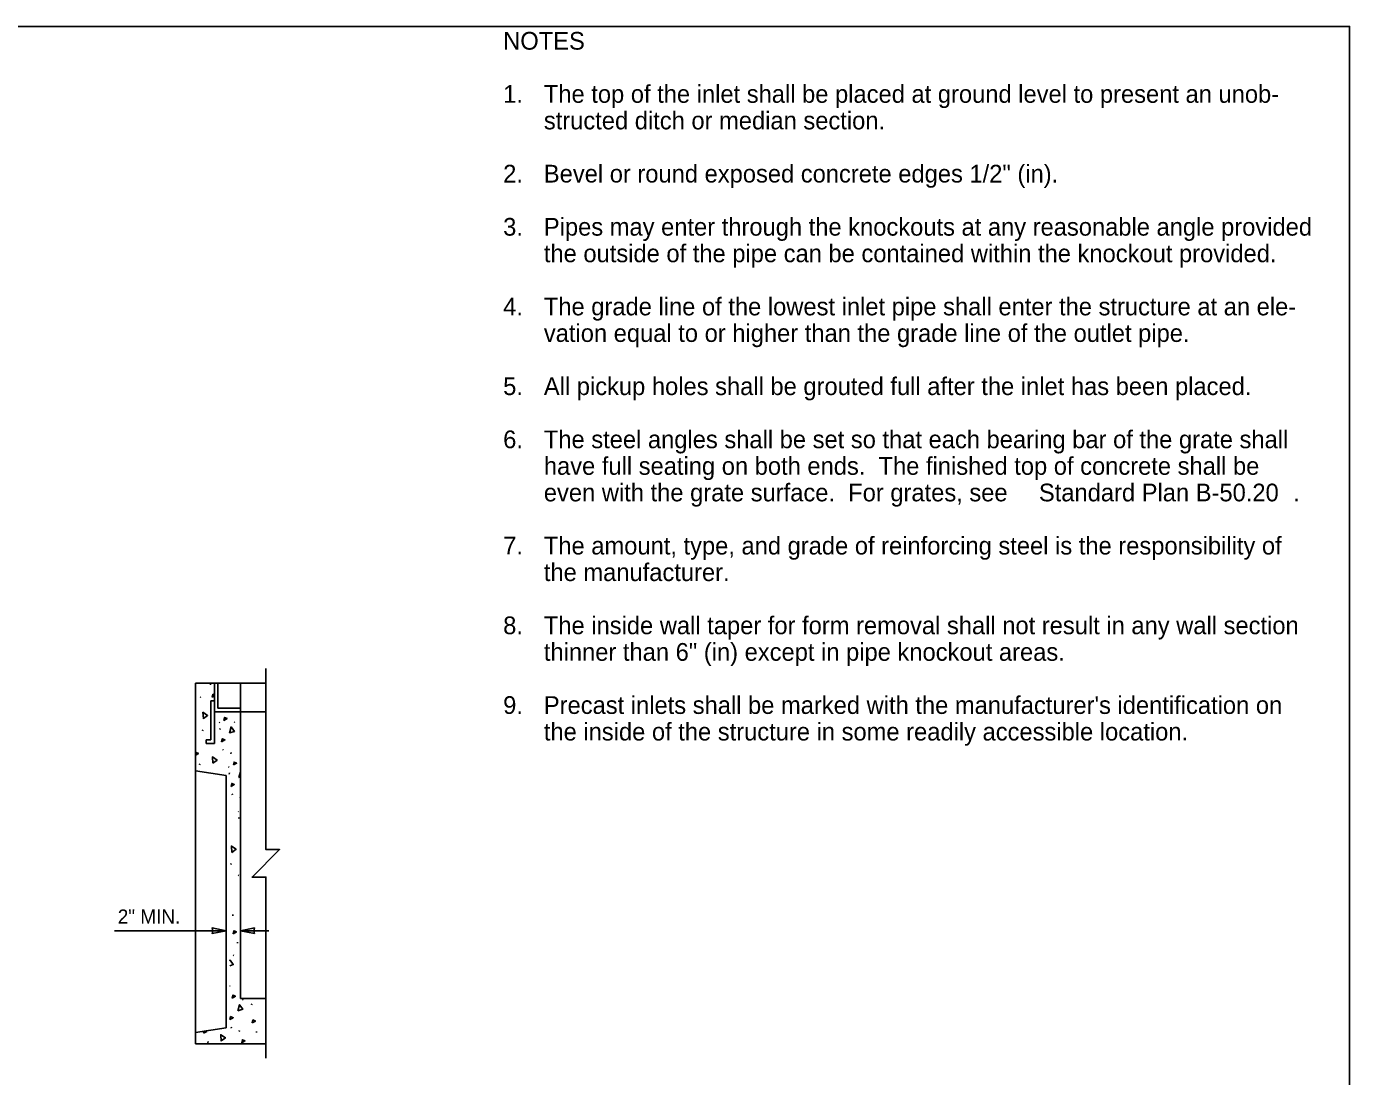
# Model space of a CAD drawing. Extents: x 99862 to 103151, y 100000 to 102076.
# Drawn here: x 101658 to 103151, y 100890 to 102076 of the extents above; entities that cross this region are included whole.
import ezdxf

# ---------------------------------------------------------------- set-up
doc = ezdxf.new("R2010")
doc.units = 0
for name, color, linetype in [('Level 1', 7, 'Continuous'), ('Level 11', 7, 'Continuous'), ('Level 15', 7, 'Continuous'), ('Level 16', 7, 'Continuous'), ('Level 17', 7, 'Continuous'), ('Level 18', 7, 'Continuous'), ('Level 20', 7, 'Continuous'), ('Level 60', 7, 'Continuous')]:
    doc.layers.add(name, color=color, linetype=linetype)

msp = doc.modelspace()

# ---------------------------------------------------------------- linework, layer by layer
at = {"layer": 'Level 1'}
msp.add_lwpolyline([(99862, 99999.5), (103151, 99999.5), (103151, 102075.5), (99862, 102075.5)], close=True, dxfattribs=at)
at = {"layer": 'Level 11'}
for p, q in [((101848.8, 101334.2), (101870.2, 101334.2)), ((101848.8, 101235), (101848.8, 101334.2)), ((101899.7, 100977.9), (101899.7, 101301.6)), ((101848.8, 101235), (101883.3, 101229.9)), ((101883.3, 101229.9), (101883.3, 100944.8)), ((101899.7, 100977.9), (101928.2, 100977.9)), ((101883.3, 100944.8), (101848.8, 100939.7)), ((101848.8, 100939.7), (101848.8, 100927)), ((101848.8, 100927), (101928.2, 100927))]:
    msp.add_line(p, q, dxfattribs=at)
at = {"layer": 'Level 15'}
for p, q in [((101757.4, 101054.5), (101883.3, 101054.5)), ((101899.7, 101054.5), (101931.7, 101054.5))]:
    msp.add_line(p, q, dxfattribs=at)
msp.add_lwpolyline([(101928.2, 101350.6), (101928.2, 101146.1), (101943.7, 101146.1), (101912.7, 101115.1), (101928.2, 101115.1), (101928.2, 100910.6)], dxfattribs=at)
for points in [[(101883.3, 101054.5), (101867.6, 101057.6), (101868.3, 101054.5), (101867.6, 101051.4)], [(101899.7, 101054.5), (101915.4, 101051.4), (101914.7, 101054.5), (101915.4, 101057.6)]]:
    msp.add_lwpolyline(points, close=True, dxfattribs=at)
at = {"layer": 'Level 16'}
for p, q in [((101865.6, 101332.1), (101865.8, 101333.3)), ((101854.2, 101318.6), (101854.8, 101318)), ((101856.7, 101280.3), (101857, 101281.5)), ((101875.5, 101290), (101876.1, 101289.4)), ((101876.2, 101281.8), (101876.5, 101283)), ((101892.5, 101290.4), (101893.1, 101289.7)), ((101879.6, 101259.2), (101880, 101258.2)), ((101888.6, 101254.4), (101888.9, 101255.6)), ((101853.4, 101241.7), (101853.6, 101242.9)), ((101886.2, 101239.7), (101886.8, 101239)), ((101886.9, 101231.4), (101887.2, 101232.6)), ((101890.3, 101208.9), (101890.7, 101207.9)), ((101899.3, 101204.1), (101899.6, 101205.3)), ((101896.9, 101189.3), (101897.5, 101188.7)), ((101897.6, 101181.1), (101897.9, 101182.3)), ((101888.8, 101129.3), (101889.1, 101130.5)), ((101897, 101117.3), (101897.6, 101116.7)), ((101890.8, 101071.5), (101891.1, 101072.7)), ((101899.5, 101079), (101899.7, 101079.7)), ((101896.2, 101040.4), (101896.4, 101041.6)), ((101891.2, 101027.1), (101891.9, 101026.5)), ((101887.5, 100991.9), (101887.6, 100992.3)), ((101901.9, 100976.8), (101902.6, 100976.1)), ((101912.2, 100970.9), (101912.5, 100972.1)), ((101889.1, 100945.6), (101889.4, 100944.6)), ((101898, 100940.8), (101898.3, 100942)), ((101917.6, 100939.7), (101917.8, 100940.9)), ((101862.8, 100928.1), (101863, 100929.3))]:
    msp.add_line(p, q, dxfattribs=at)
for points in [[(101867.6, 101318.2), (101868.4, 101321.5), (101870.2, 101320.7)], [(101870.2, 101319.6), (101867.6, 101318.2)], [(101857.7, 101293.9), (101857.2, 101301.1), (101862.5, 101297.5), (101857.8, 101294)], [(101880.9, 101292), (101881.7, 101295.4), (101884.5, 101294.1), (101880.9, 101292)], [(101887.1, 101277.7), (101889, 101284.6), (101892.8, 101279.5), (101887.2, 101277.8)], [(101878.3, 101267.9), (101879.1, 101271.2), (101882, 101269.9), (101878.3, 101267.9)], [(101848.8, 101253.3), (101849.4, 101255.8), (101852.2, 101254.5), (101848.8, 101252.6)], [(101868.4, 101243.6), (101867.9, 101250.7), (101873.2, 101247.2), (101868.5, 101243.7)], [(101891.6, 101241.7), (101892.4, 101245), (101895.2, 101243.7), (101891.6, 101241.7)], [(101889, 101217.5), (101889.8, 101220.9), (101892.6, 101219.6), (101889, 101217.5)], [(101897.8, 101227.4), (101899.7, 101234.1)], [(101899.7, 101228), (101897.9, 101227.4)], [(101889.8, 101142.9), (101889.3, 101150.1), (101894.6, 101146.5), (101889.9, 101143)], [(101891.4, 101051.1), (101892.2, 101054.5), (101895, 101053.2), (101891.4, 101051.1)], [(101887.5, 101020.3), (101887.8, 101021.3), (101891.5, 101016.2), (101887.5, 101014.9)], [(101890.3, 100978.4), (101891.1, 100981.8), (101893.9, 100980.5), (101890.3, 100978.4)], [(101896.5, 100964.1), (101898.5, 100971), (101902.2, 100965.8), (101896.6, 100964.1)], [(101887.7, 100954.2), (101888.5, 100957.6), (101891.4, 100956.3), (101887.7, 100954.2)], [(101912.8, 100950.5), (101913.6, 100953.8), (101916.4, 100952.5), (101912.8, 100950.5)], [(101860.4, 100941.5), (101861.6, 100940.9), (101858, 100938.8)], [(101858, 100938.8), (101858.6, 100941.2)], [(101877.8, 100930), (101877.3, 100937.1), (101882.6, 100933.6), (101877.9, 100930.1)], [(101901, 100928.1), (101901.8, 100931.4), (101904.6, 100930.1), (101901, 100928.1)]]:
    msp.add_lwpolyline(points, dxfattribs=at)
at = {"layer": 'Level 17'}
msp.add_line((101848.8, 101235), (101848.8, 100939.7), dxfattribs=at)
at = {"layer": 'Level 18'}
for p, q in [((101870.2, 101266), (101870.2, 101334.2)), ((101870.2, 101334.2), (101928.2, 101334.2)), ((101874.2, 101305.7), (101874.2, 101334.2)), ((101899.7, 101301.6), (101899.7, 101334.2)), ((101866.1, 101270.1), (101866.1, 101313.9)), ((101866.1, 101313.9), (101870.2, 101313.9)), ((101870.2, 101301.6), (101928.2, 101301.6)), ((101874.2, 101305.7), (101899.7, 101305.7)), ((101866.1, 101270.1), (101861, 101270.1)), ((101861, 101266), (101861, 101270.1)), ((101870.2, 101266), (101861, 101266))]:
    msp.add_line(p, q, dxfattribs=at)
at = {"layer": 'Level 60'}
msp.add_line((103151, 102075.5), (103151, 102075.5), dxfattribs=at)

# ---------------------------------------------------------------- texts
at = {"layer": 'Level 20'}
for s, height, p in [('NOTES', 20, (102196, 102049.3)), ('1.', 20, (102196, 101989.3)), ('The top of the inlet shall be placed at ground level to present an unob-', 20, (102241.9, 101989.3)), ('structed ditch or median section.', 20, (102241.9, 101959.3)), ('2.', 20, (102196, 101899.3)), ('Bevel or round exposed concrete edges 1/2" (in).', 20, (102241.9, 101899.3)), ('3.', 20, (102196, 101839.3)), ('Pipes may enter through the knockouts at any reasonable angle provided', 20, (102241.9, 101839.3)), ('the outside of the pipe can be contained within the knockout provided.', 20, (102241.9, 101809.3)), ('4.', 20, (102196, 101749.3)), ('The grade line of the lowest inlet pipe shall enter the structure at an ele-', 20, (102241.9, 101749.3)), ('vation equal to or higher than the grade line of the outlet pipe.', 20, (102241.9, 101719.3)), ('5.', 20, (102196, 101659.3)), ('All pickup holes shall be grouted full after the inlet has been placed.', 20, (102241.9, 101659.3)), ('6.', 20, (102196, 101599.3)), ('The steel angles shall be set so that each bearing bar of the grate shall ', 20, (102241.9, 101599.3)), ('have full seating on both ends.  The finished top of concrete shall be ', 20, (102241.9, 101569.3)), ('even with the grate surface.  For grates, see ', 20, (102241.9, 101539.3)), ('Standard Plan B-50.20', 20, (102800.5, 101539.3)), ('.', 20, (103087.3, 101539.3)), ('7.', 20, (102196, 101479.3)), ('The amount, type, and grade of reinforcing steel is the responsibility of', 20, (102241.9, 101479.3)), ('the manufacturer.', 20, (102241.9, 101449.3)), ('8.', 20, (102196, 101389.3)), ('The inside wall taper for form removal shall not result in any wall section', 20, (102241.9, 101389.3)), ('thinner than 6" (in) except in pipe knockout areas.', 20, (102241.9, 101359.3)), ('9.', 20, (102196, 101299.3)), ("Precast inlets shall be marked with the manufacturer's identification on", 20, (102241.9, 101299.3)), ('the inside of the structure in some readily accessible location.', 20, (102241.9, 101269.3)), ('2" MIN.', 16, (101761.1, 101062.5))]:
    msp.add_text(s, height=height, dxfattribs=at).set_placement(p)

doc.saveas('drawing.dxf')
